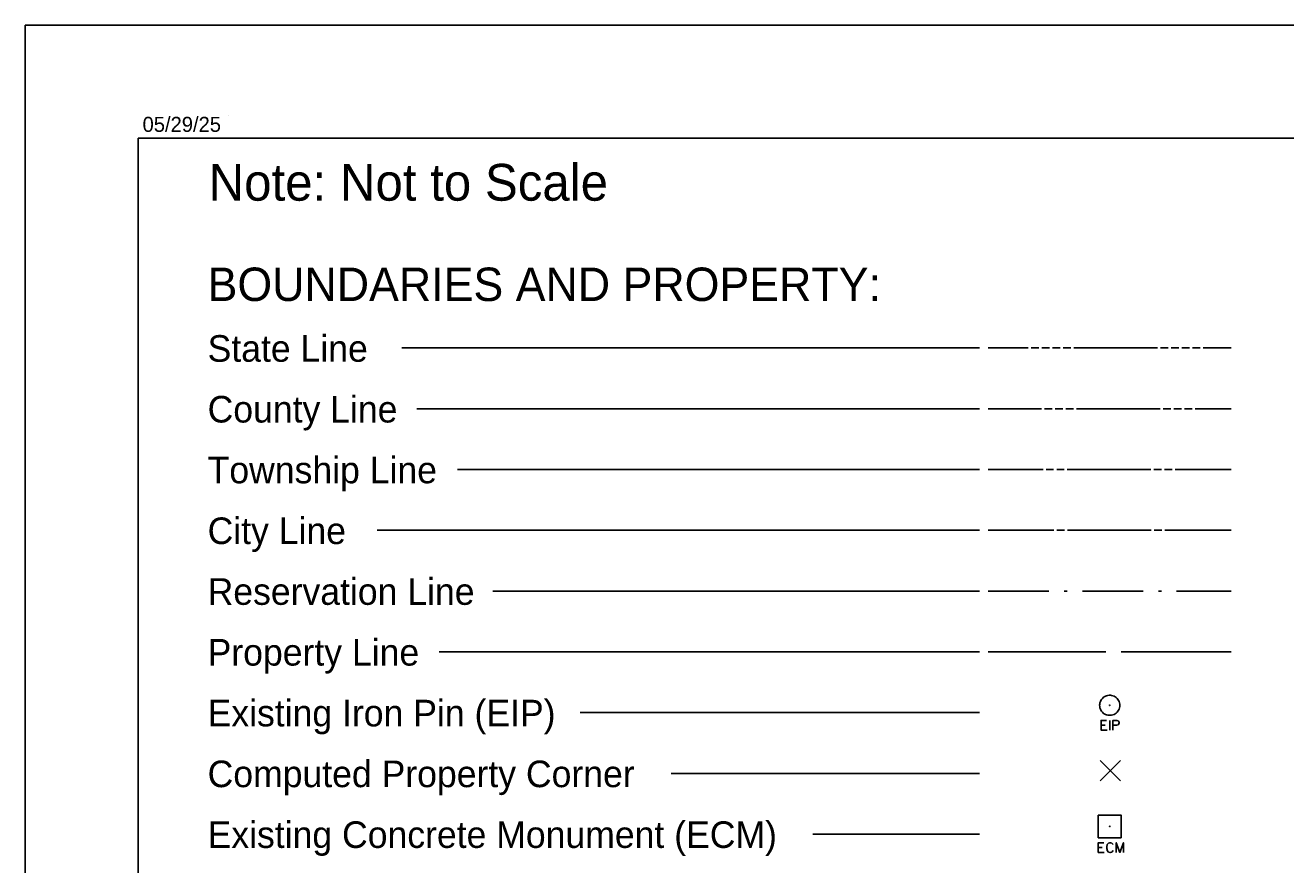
# Model space of a CAD drawing. Extents: x 754056.72 to 754059.56, y 596603.78 to 596605.61.
# Drawn here: x 754056.725 to 754057.422, y 596605.147 to 596605.612 of the extents above; entities that cross this region are included whole.
import ezdxf

# ---------------------------------------------------------------- set-up
doc = ezdxf.new("R2010")
doc.units = 0
for name, color, linetype in [('Sheet_Plan', 7, 'Continuous'), ('Sheet_Plot_Border_Outside_CELL', 7, 'Continuous'), ('Sheet_Symbology', 7, 'Continuous'), ('z - Construction', 7, 'Continuous')]:
    doc.layers.add(name, color=color, linetype=linetype)

msp = doc.modelspace()

# ---------------------------------------------------------------- linework, layer by layer
at = {"layer": 'Sheet_Plan'}
for p, q in [((754056.83727, 596605.56165), (754056.83727, 596605.56165)), ((754056.78734, 596603.84076), (754056.78733, 596605.54909)), ((754059.49567, 596605.54909), (754056.78733, 596605.54909))]:
    msp.add_line(p, q, dxfattribs=at)
at = {"layer": 'Sheet_Plot_Border_Outside_CELL'}
msp.add_lwpolyline([(754056.72484, 596605.61159), (754059.55817, 596605.61159), (754059.55817, 596603.77826), (754056.72484, 596603.77826)], close=True, dxfattribs=at)
at = {"layer": 'Sheet_Symbology'}
for p, q in [((754057.25263, 596605.43298), (754056.93316, 596605.43298)), ((754057.25747, 596605.43298), (754057.27967, 596605.43298)), ((754057.28135, 596605.43298), (754057.28555, 596605.43298)), ((754057.28723, 596605.43298), (754057.29144, 596605.43298)), ((754057.29312, 596605.43298), (754057.29732, 596605.43298)), ((754057.299, 596605.43298), (754057.30321, 596605.43298)), ((754057.30489, 596605.43298), (754057.35113, 596605.43298)), ((754057.35281, 596605.43298), (754057.35702, 596605.43298)), ((754057.3587, 596605.43298), (754057.3629, 596605.43298)), ((754057.36458, 596605.43298), (754057.36879, 596605.43298)), ((754057.37047, 596605.43298), (754057.37467, 596605.43298)), ((754057.37636, 596605.43298), (754057.39199, 596605.43298)), ((754057.25263, 596605.39935), (754056.94155, 596605.39935)), ((754057.25747, 596605.39935), (754057.28704, 596605.39935)), ((754057.28873, 596605.39935), (754057.29293, 596605.39935)), ((754057.29461, 596605.39935), (754057.29881, 596605.39935)), ((754057.3005, 596605.39935), (754057.3047, 596605.39935)), ((754057.30638, 596605.39935), (754057.35262, 596605.39935)), ((754057.35431, 596605.39935), (754057.35851, 596605.39935)), ((754057.36019, 596605.39935), (754057.3644, 596605.39935)), ((754057.36608, 596605.39935), (754057.37028, 596605.39935)), ((754057.37196, 596605.39935), (754057.39199, 596605.39935)), ((754057.25263, 596605.36572), (754056.96391, 596605.36572)), ((754057.25747, 596605.36572), (754057.28782, 596605.36572)), ((754057.2895, 596605.36572), (754057.29371, 596605.36572)), ((754057.29539, 596605.36572), (754057.29959, 596605.36572)), ((754057.30127, 596605.36572), (754057.34752, 596605.36572)), ((754057.3492, 596605.36572), (754057.3534, 596605.36572)), ((754057.35508, 596605.36572), (754057.35929, 596605.36572)), ((754057.36097, 596605.36572), (754057.39199, 596605.36572)), ((754057.25263, 596605.33209), (754056.91957, 596605.33209)), ((754057.25747, 596605.33209), (754057.29385, 596605.33209)), ((754057.29554, 596605.33209), (754057.29974, 596605.33209)), ((754057.30142, 596605.33209), (754057.34766, 596605.33209)), ((754057.34935, 596605.33209), (754057.35355, 596605.33209)), ((754057.35523, 596605.33209), (754057.39199, 596605.33209)), ((754057.25263, 596605.29846), (754056.98346, 596605.29846)), ((754057.25747, 596605.29846), (754057.2911, 596605.29846)), ((754057.29951, 596605.29846), (754057.30119, 596605.29846)), ((754057.3096, 596605.29846), (754057.34323, 596605.29846)), ((754057.35164, 596605.29846), (754057.35332, 596605.29846)), ((754057.36173, 596605.29846), (754057.39199, 596605.29846)), ((754057.25263, 596605.26483), (754056.95388, 596605.26483)), ((754057.25747, 596605.26483), (754057.32263, 596605.26483)), ((754057.33104, 596605.26483), (754057.39199, 596605.26483)), ((754057.25263, 596605.23119), (754057.03187, 596605.23119)), ((754057.32475, 596605.22153), (754057.32475, 596605.22691)), ((754057.31992, 596605.22424), (754057.32212, 596605.22424)), ((754057.33064, 596605.19349), (754057.31953, 596605.20461)), ((754057.31953, 596605.19349), (754057.33064, 596605.20461)), ((754057.25263, 596605.19756), (754057.08205, 596605.19756)), ((754057.25263, 596605.16393), (754057.16044, 596605.16393)), ((754057.31838, 596605.15653), (754057.32059, 596605.15653))]:
    msp.add_line(p, q, dxfattribs=at)
for points in [[(754057.33027, 596605.23523), (754057.33023, 596605.23595), (754057.33009, 596605.23661), (754057.32987, 596605.23729), (754057.3296, 596605.23791), (754057.3292, 596605.23849), (754057.32875, 596605.23903), (754057.32826, 596605.23952), (754057.32768, 596605.23992), (754057.3271, 596605.24028), (754057.32643, 596605.2405), (754057.32576, 596605.24068), (754057.32509, 596605.24077), (754057.32437, 596605.24077), (754057.32366, 596605.24068), (754057.32299, 596605.2405), (754057.32236, 596605.24028), (754057.32174, 596605.23992), (754057.32116, 596605.23952), (754057.32066, 596605.23903), (754057.32022, 596605.23849), (754057.31986, 596605.23791), (754057.31955, 596605.23729), (754057.31932, 596605.23661), (754057.31919, 596605.23595), (754057.31915, 596605.23523), (754057.31919, 596605.23452), (754057.31932, 596605.23385), (754057.31955, 596605.23317), (754057.31986, 596605.23255), (754057.32022, 596605.23197), (754057.32066, 596605.23143), (754057.32116, 596605.23094), (754057.32174, 596605.23054), (754057.32236, 596605.23018), (754057.32299, 596605.22996), (754057.32366, 596605.22978), (754057.32437, 596605.22969), (754057.32509, 596605.22969), (754057.32576, 596605.22978), (754057.32643, 596605.22996), (754057.3271, 596605.23018), (754057.32768, 596605.23054), (754057.32826, 596605.23094), (754057.32875, 596605.23143), (754057.3292, 596605.23197), (754057.3296, 596605.23255), (754057.32987, 596605.23317), (754057.33009, 596605.23385), (754057.33023, 596605.23452), (754057.33027, 596605.23523)], [(754057.32482, 596605.23536), (754057.32469, 596605.23541), (754057.3246, 596605.23532), (754057.32455, 596605.23519), (754057.32464, 596605.2351), (754057.32478, 596605.23505), (754057.32487, 596605.23514), (754057.32491, 596605.23527), (754057.32482, 596605.23536)], [(754057.32301, 596605.22691), (754057.31992, 596605.22691), (754057.31992, 596605.22153), (754057.32322, 596605.22153)], [(754057.32653, 596605.22153), (754057.32653, 596605.22691), (754057.32869, 596605.22691), (754057.32932, 596605.22669), (754057.32988, 596605.22585), (754057.32988, 596605.22534), (754057.32937, 596605.22449), (754057.32869, 596605.22428), (754057.32653, 596605.22428)], [(754057.31842, 596605.17451), (754057.33102, 596605.17451), (754057.33102, 596605.16191), (754057.31842, 596605.16191), (754057.31842, 596605.17451)], [(754057.32469, 596605.16837), (754057.32463, 596605.1683), (754057.32463, 596605.16818), (754057.32475, 596605.16805), (754057.32488, 596605.16812), (754057.32494, 596605.16824), (754057.32481, 596605.16837), (754057.32469, 596605.16837)], [(754057.32148, 596605.1592), (754057.31838, 596605.1592), (754057.31838, 596605.15382), (754057.32169, 596605.15382)], [(754057.32656, 596605.15814), (754057.32588, 596605.15903), (754057.32521, 596605.1592), (754057.32474, 596605.1592), (754057.3241, 596605.15903), (754057.32338, 596605.15814), (754057.32321, 596605.15696), (754057.32321, 596605.15632), (754057.32321, 596605.1559), (754057.32326, 596605.15552), (754057.32338, 596605.15484), (754057.3241, 596605.15399), (754057.32474, 596605.15382), (754057.32512, 596605.15382), (754057.32584, 596605.15399), (754057.32656, 596605.15484)], [(754057.3283, 596605.15382), (754057.3283, 596605.1592), (754057.33033, 596605.15382), (754057.33228, 596605.1592), (754057.33228, 596605.15382)]]:
    msp.add_lwpolyline(points, dxfattribs=at)
at = {"layer": 'z - Construction'}
for p, q in [((754059.55817, 596605.61159), (754056.72484, 596605.61159)), ((754056.72484, 596605.61159), (754056.72484, 596603.77826))]:
    msp.add_line(p, q, dxfattribs=at)

# ---------------------------------------------------------------- texts
at = {"layer": 'Sheet_Plan'}
msp.add_text('05/29/25', height=0.008333, rotation=0, dxfattribs=at).set_placement((754056.78976, 596605.55255))
at = {"layer": 'Sheet_Symbology'}
for s, height, p in [('Note: Not to Scale', 0.0203596, (754056.82628, 596605.51448)), ('BOUNDARIES AND PROPERTY:', 0.0184972, (754056.82571, 596605.45896)), ('State Line', 0.014714, (754056.82573, 596605.42535)), ('County Line', 0.0147137, (754056.82573, 596605.39172)), ('Township Line', 0.0147137, (754056.82573, 596605.35809)), ('City Line', 0.014714, (754056.82573, 596605.32446)), ('Reservation Line', 0.0147137, (754056.82573, 596605.29083)), ('Property Line', 0.0147137, (754056.82573, 596605.2572)), ('Existing Iron Pin (EIP)', 0.0147137, (754056.82573, 596605.22356)), ('Computed Property Corner', 0.0147137, (754056.82573, 596605.18993)), ('Existing Concrete Monument (ECM)', 0.0147137, (754056.82573, 596605.1563))]:
    msp.add_text(s, height=height, dxfattribs=at).set_placement(p)

doc.saveas('drawing.dxf')
